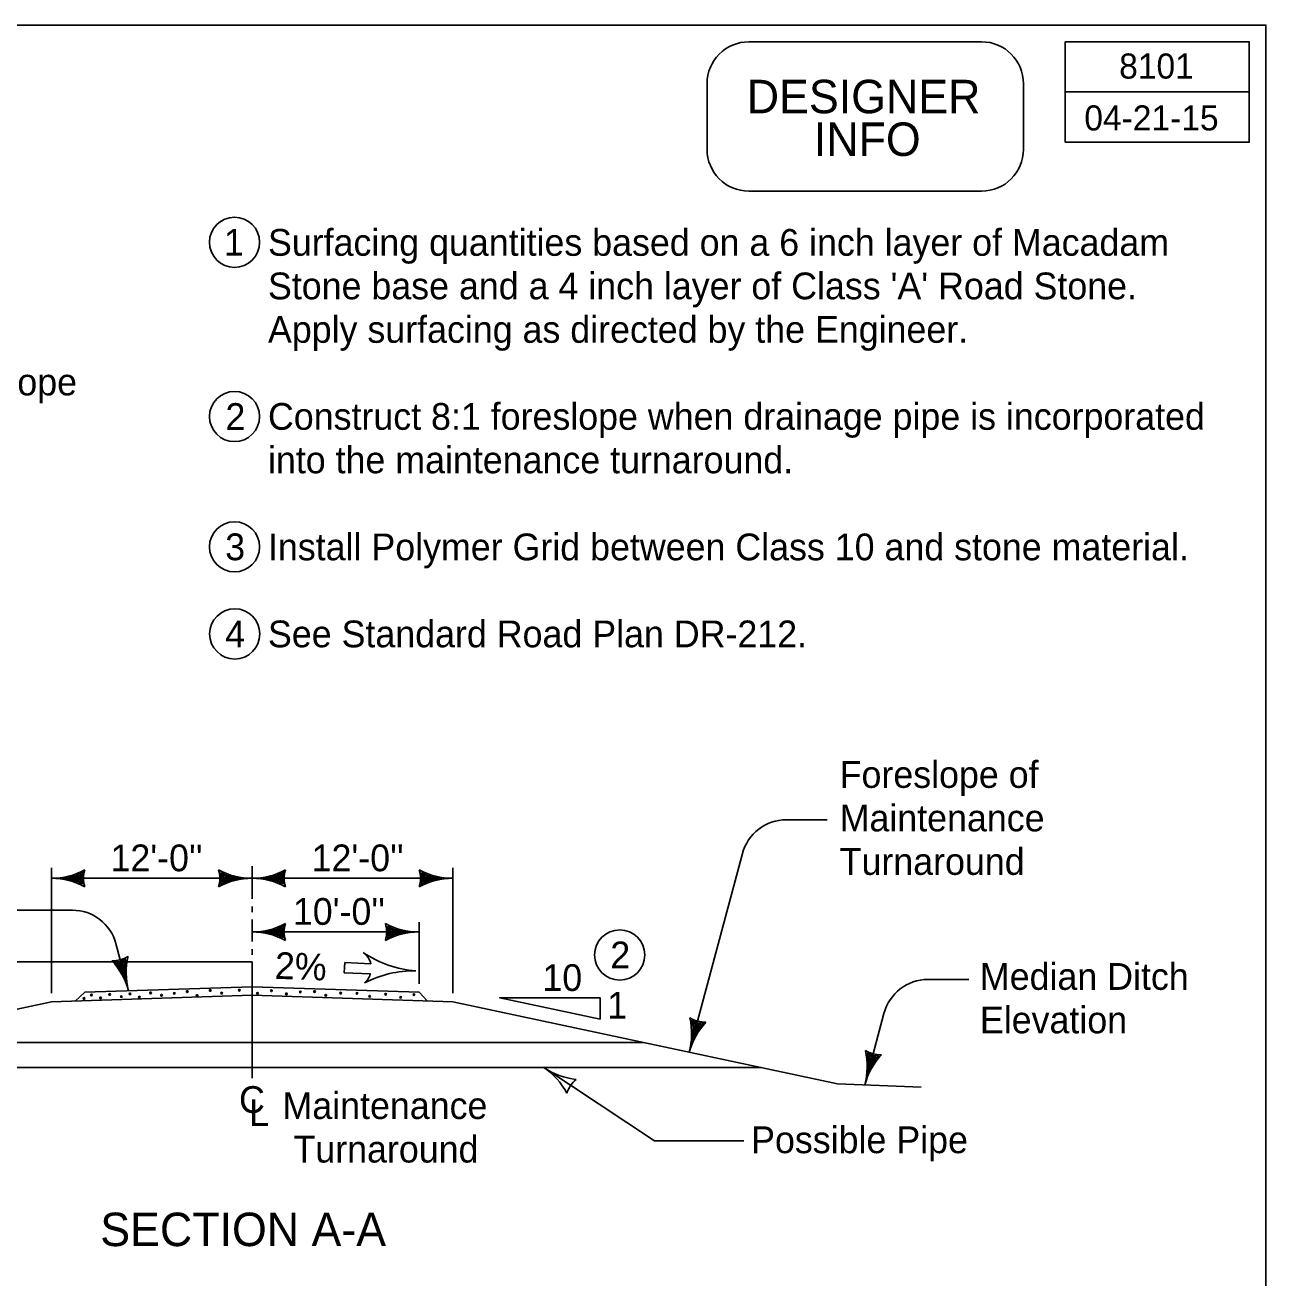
# Model space of a CAD drawing. Extents: x -772 to 772, y -957 to 657.
# Drawn here: x 31 to 772, y -91 to 657 of the extents above; entities that cross this region are included whole.
import ezdxf

# ---------------------------------------------------------------- set-up
doc = ezdxf.new("R2010")
doc.units = 0
for name, color, linetype in [('dsnCellElements', 7, 'Continuous'), ('dsnStdLabel', 7, 'Continuous'), ('dsnStdNameDate', 7, 'Continuous'), ('dsnStdNote', 7, 'Continuous'), ('Level 2', 7, 'Continuous'), ('Level 3', 7, 'Continuous'), ('Level 4', 7, 'Continuous')]:
    doc.layers.add(name, color=color, linetype=linetype)

msp = doc.modelspace()

# ---------------------------------------------------------------- linework, layer by layer
at = {"layer": 'dsnCellElements'}
for points in [[(-772.5, 657.5), (-772.5, -657.5), (772.5, -657.5), (772.5, 657.5), (-772.5, 657.5)], [(762.5, 647.5), (762.5, 587.5), (652.5, 587.5), (652.5, 647.5), (762.5, 647.5), (762.5, 617.5), (652.5, 617.5)]]:
    msp.add_lwpolyline(points, dxfattribs=at)
at = {"layer": 'dsnStdLabel'}
for points in [[(463.33, 647.5), (602.5, 647.5)], [(602.5, 647.5), (463.33, 647.5)], [(438.33, 583.22), (438.33, 622.5)], [(438.33, 622.5), (438.33, 583.22)], [(627.5, 622.5), (627.5, 583.22)], [(627.5, 583.22), (627.5, 622.5)], [(602.5, 558.22), (463.33, 558.22)], [(463.33, 558.22), (602.5, 558.22)]]:
    msp.add_lwpolyline(points, dxfattribs=at)
for centre, start, end in [((463.33, 622.5), 90, 180), ((463.33, 622.5), 90, 180), ((602.5, 622.5), 0, 90), ((602.5, 622.5), 0, 90), ((463.33, 583.22), 180, 270), ((463.33, 583.22), 180, 270), ((602.5, 583.22), 270, 0), ((602.5, 583.22), 270, 0)]:
    msp.add_arc(centre, 25, start, end, dxfattribs=at)
at = {"layer": 'dsnStdNote'}
for centre in [(155.8, 527.68), (155.8, 423.5), (155.8, 345.64), (155.92, 293.59), (386.11, 101.71)]:
    msp.add_circle(centre, 15, dxfattribs=at)
at = {"layer": 'Level 2'}
for p, q in [((510.15, 182.51), (485.77, 182.52)), ((459.47, 162.25), (432.64, 62.14)), ((46.28, 78.78), (46.28, 153.69)), ((166.28, 135.24), (166.28, 154.69)), ((286.28, 78.78), (286.28, 153.78)), ((46.28, 147.52), (286.28, 147.52)), ((46.28, 147.52), (65.5, 147.52)), ((166.28, 147.52), (147.06, 147.52)), ((166.28, 147.52), (185.5, 147.52)), ((286.28, 147.52), (267.06, 147.52)), ((33.91, 128.48), (-11.18, 128.48)), ((33.91, 128.48), (58.91, 128.48)), ((166.28, 127.36), (166.28, 130.67)), ((166.28, 109.71), (166.28, 122.87)), ((266.28, 106.29), (266.28, 121.29)), ((166.28, 115.44), (266.28, 115.44)), ((166.3, 115.44), (185.52, 115.44)), ((265.98, 115.44), (246.76, 115.44)), ((84.89, 108.47), (87.48, 98.81)), ((166.28, 101.83), (166.28, 105.1)), ((266.28, 84.38), (266.28, 111.29)), ((166.28, 97.69), (-39.09, 97.69)), ((92.45, 80.24), (87.48, 98.81)), ((166.28, 28.06), (166.28, 97.69)), ((166.28, 82.69), (66.28, 79.38)), ((166.28, 82.69), (266.28, 79.38)), ((594.77, 87.05), (570.38, 87.05)), ((166.28, 77.69), (46.28, 73.69)), ((66.28, 79.38), (60.48, 74.17)), ((166.28, 77.69), (286.28, 73.69)), ((266.28, 79.38), (271.05, 74.2)), ((314.37, 76.11), (374.37, 76.11)), ((314.37, 76.11), (374.37, 63.33)), ((374.37, 76.11), (374.37, 63.33)), ((46.28, 73.69), (-183.72, 24.69)), ((271.05, 74.2), (271.05, 74.2)), ((286.28, 73.69), (516.28, 24.69)), ((427.67, 43.57), (432.64, 62.14)), ((544.08, 66.79), (537.6, 42.61)), ((532.62, 24.04), (537.6, 42.61)), ((516.28, 24.69), (566.28, 22.69))]:
    msp.add_line(p, q, dxfattribs=at)
for points in [[(65.11, 143.96), (64.39, 147.54), (65.14, 151.15), (60.84, 149.07), (54.02, 147.54), (61.35, 145.83), (64.51, 144.42), (63.73, 147.54), (64.03, 149.85), (61.2, 148.5), (57.42, 147.54), (61.44, 146.37), (63.55, 145.65), (63.16, 148.71), (60.36, 147.54), (62.56, 146.85), (62.59, 147.9), (61.56, 147.57)], [(147.46, 151.08), (148.18, 147.51), (147.43, 143.9), (151.72, 145.98), (158.55, 147.51), (151.21, 149.22), (148.06, 150.63), (148.84, 147.51), (148.54, 145.19), (151.36, 146.55), (155.15, 147.51), (151.12, 148.68), (149.02, 149.4), (149.41, 146.34), (152.21, 147.51), (150.01, 148.2), (149.98, 147.15), (151, 147.48)], [(185.11, 143.96), (184.39, 147.54), (185.14, 151.15), (180.84, 149.07), (174.02, 147.54), (181.35, 145.83), (184.51, 144.42), (183.73, 147.54), (184.03, 149.85), (181.2, 148.5), (177.42, 147.54), (181.44, 146.37), (183.55, 145.65), (183.16, 148.71), (180.36, 147.54), (182.56, 146.85), (182.59, 147.9), (181.56, 147.57)], [(267.46, 151.08), (268.18, 147.51), (267.43, 143.9), (271.72, 145.98), (278.55, 147.51), (271.21, 149.22), (268.06, 150.63), (268.84, 147.51), (268.54, 145.19), (271.36, 146.55), (275.15, 147.51), (271.12, 148.68), (269.02, 149.4), (269.41, 146.34), (272.21, 147.51), (270.01, 148.2), (269.98, 147.15), (271, 147.48)], [(185.13, 111.88), (184.4, 115.46), (185.16, 119.06), (180.86, 116.99), (174.04, 115.46), (181.37, 113.75), (184.53, 112.33), (183.74, 115.46), (184.04, 117.77), (181.22, 116.42), (177.43, 115.46), (181.46, 114.29), (183.56, 113.57), (183.17, 116.63), (180.38, 115.46), (182.57, 114.77), (182.6, 115.82), (181.58, 115.49)], [(247.15, 119), (247.87, 115.43), (247.12, 111.82), (251.42, 113.89), (258.24, 115.43), (250.91, 117.14), (247.75, 118.55), (248.54, 115.43), (248.23, 113.11), (251.06, 114.46), (254.85, 115.43), (250.82, 116.6), (248.72, 117.32), (249.11, 114.25), (251.9, 115.43), (249.71, 116.12), (249.68, 115.07), (250.7, 115.4)], [(91.02, 99.35), (87.75, 97.73), (84.07, 97.52), (87.19, 93.91), (90.43, 87.72), (90.19, 95.24), (90.74, 98.65), (87.92, 97.09), (85.61, 96.78), (87.65, 94.4), (89.56, 90.99), (89.65, 95.19), (89.8, 97.41), (86.94, 96.24), (88.79, 93.84), (88.89, 96.14), (87.87, 95.89), (88.45, 94.99)], [(429.1, 62.68), (432.37, 61.06), (436.05, 60.85), (432.93, 57.23), (429.69, 51.04), (429.93, 58.57), (429.38, 61.98), (432.2, 60.42), (434.51, 60.11), (432.47, 57.73), (430.56, 54.32), (430.47, 58.52), (430.32, 60.73), (433.18, 59.56), (431.33, 57.17), (431.23, 59.47), (432.25, 59.22), (431.67, 58.32)], [(534.06, 43.15), (537.32, 41.52), (541, 41.32), (537.89, 37.7), (534.64, 31.51), (534.88, 39.03), (534.34, 42.45), (537.15, 40.89), (539.47, 40.58), (537.43, 38.2), (535.52, 34.79), (535.43, 38.98), (535.28, 41.2), (538.14, 40.03), (536.28, 37.63), (536.18, 39.93), (537.21, 39.69), (536.62, 38.79)], [(460.41, -9.35), (406.87, -9.35), (340.73, 34.39)]]:
    msp.add_lwpolyline(points, dxfattribs=at)
for centre, radius, start, end in [((485.87, 155.18), 27.34, 90.21208, 165.00024), ((46.28, 190.02), 42.5, 270, 298.07249), ((81.92, 147.52), 16.42, 162.26665, 197.73335), ((130.65, 147.52), 16.42, 342.26665, 17.73335), ((166.28, 190.02), 42.5, 241.92751, 270), ((166.28, 190.02), 42.5, 270, 298.07249), ((201.92, 147.52), 16.42, 162.26665, 197.73335), ((250.65, 147.52), 16.42, 342.26665, 17.73335), ((286.28, 190.02), 42.5, 241.92751, 270), ((46.28, 105.02), 42.5, 61.92751, 90), ((166.28, 105.02), 42.5, 90, 118.07249), ((166.28, 105.02), 42.5, 61.92751, 90), ((286.28, 105.02), 42.5, 90, 118.07249), ((58.81, 101.48), 27, 14.99976, 89.78792), ((166.3, 157.94), 42.5, 270, 298.07249), ((201.93, 115.44), 16.42, 162.26665, 197.73335), ((230.34, 115.44), 16.42, 342.26665, 17.73335), ((265.98, 157.94), 42.5, 241.92751, 270), ((166.3, 72.94), 42.5, 61.92751, 90), ((265.98, 72.94), 42.5, 90, 118.07249), ((83.23, 114.67), 16.42, 267.26665, 302.73335), ((51.4, 69.25), 42.5, 15, 43.07249), ((133.5, 91.25), 42.5, 166.92751, 195), ((570.49, 59.72), 27.34, 90.21208, 165.00024), ((386.62, 54.57), 42.5, 345, 13.07249), ((468.72, 32.57), 42.5, 136.92751, 165), ((436.89, 77.99), 16.42, 237.26665, 272.73335), ((491.57, 35.04), 42.5, 345, 13.07249), ((573.68, 13.04), 42.5, 136.92751, 165), ((541.85, 58.46), 16.42, 237.26665, 272.73335), ((364.49, 69.63), 42.5, 236, 264.07249), ((316.96, -0.84), 42.5, 27.92751, 56), ((370.27, 14.47), 16.42, 128.26665, 163.73335)]:
    msp.add_arc(centre, radius, start, end, dxfattribs=at)
at = {"layer": 'Level 3'}
for centre in [(65.75, 75.71), (70.23, 77.78), (75.67, 76.03), (81.11, 78.1), (88.14, 76.82), (93.26, 78.42), (98.86, 76.51), (105.58, 79.06), (112.13, 77.62), (119.81, 78.74), (127.49, 79.86), (133.41, 77.46), (141.24, 80.5), (148.12, 78.9), (158.68, 80.66), (169.55, 78.74), (177.87, 80.34), (186.82, 78.42), (195.14, 79.54), (203.62, 79.86), (210.34, 77.62), (219.29, 78.9), (229.05, 78.74), (236.56, 76.98), (246.16, 78.26), (255.12, 76.35), (263.11, 77.94)]:
    msp.add_circle(centre, 0.5, dxfattribs=at)
at = {"layer": 'Level 4'}
for p, q in [((221.69, 97.11), (221.43, 91.11)), ((221.43, 91.11), (237.02, 90.43)), ((237.29, 96.43), (221.69, 97.11)), ((-67.78, 49.39), (400.35, 49.39)), ((-138.19, 34.39), (470.75, 34.39))]:
    msp.add_line(p, q, dxfattribs=at)
msp.add_lwpolyline([(374.37, 63.33), (374.37, 76.11), (314.37, 76.11)], close=True, dxfattribs=at)
for centre, radius, start, end in [((268.89, 156.56), 64.48, 235.78622, 265.81577), ((226.29, 93.9), 11.29, 12.92156, 55.7826), ((263.26, 27.78), 64.48, 89.18423, 117.42857), ((227.04, 92.99), 10.31, 309.27396, 345.65199)]:
    msp.add_arc(centre, radius, start, end, dxfattribs=at)

# ---------------------------------------------------------------- texts
at = {"layer": 'dsnStdLabel'}
for s, p in [('DESIGNER', (462.08, 604.78)), ('INFO', (502.18, 579.28))]:
    msp.add_text(s, height=20, dxfattribs=at).set_placement(p)
at = {"layer": 'dsnStdNameDate'}
for s, p in [('8101', (684.73, 625.5)), ('04-21-15', (663.89, 594.5))]:
    msp.add_text(s, height=15, dxfattribs=at).set_placement(p)
at = {"layer": 'Level 3'}
for s, height, p in [('1', 16, (149.43, 519.64)), ('Surfacing quantities based on a 6 inch layer of Macadam ', 16, (175.79, 519.59)), ("Stone base and a 4 inch layer of Class 'A' Road Stone.", 16, (175.79, 493.59)), ('Apply surfacing as directed by the Engineer.', 16, (175.79, 467.59)), ('Foreslope', 16, (-33.52, 436.16)), ('2', 16, (150.37, 415.5)), ('Construct 8:1 foreslope when drainage pipe is incorporated ', 16, (175.79, 415.59)), ('into the maintenance turnaround.', 16, (175.79, 389.59)), ('3', 16, (150.21, 337.64)), ('Install Polymer Grid between Class 10 and stone material.', 16, (175.79, 337.59)), ('4', 16, (150.25, 285.59)), ('See Standard Road Plan DR-212.', 16, (175.79, 285.59)), ('                                         DR-212', 16, (174.74, 285.59)), ('Foreslope of', 16, (517.61, 201.57)), ('Maintenance', 16, (517.61, 175.57)), ("12'-0''", 16, (81.64, 151.72)), ("12'-0''", 16, (201.88, 151.73)), ('Turnaround', 16, (517.61, 149.57)), ("10'-0''", 16, (190.68, 119.72)), ('2', 16, (380.49, 93.71)), ('Median Ditch', 16, (601.46, 80.86)), ('10', 16, (339.87, 80.17)), ('1', 16, (378.61, 63.6)), ('Elevation', 16, (601.46, 54.86)), ('C', 16, (158.48, 7.29)), ('L', 16, (164.52, -0.59)), ('Maintenance', 16, (184.48, 3.65)), ('Possible Pipe', 16, (464.67, -16.76)), ('Turnaround', 16, (191.04, -22.35)), ('SECTION A-A', 20, (75.52, -72.31))]:
    msp.add_text(s, height=height, dxfattribs=at).set_placement(p)
msp.add_text('2%', height=16, rotation=357.99882, dxfattribs=at).set_placement((179.69, 87.47))

doc.saveas('drawing.dxf')
